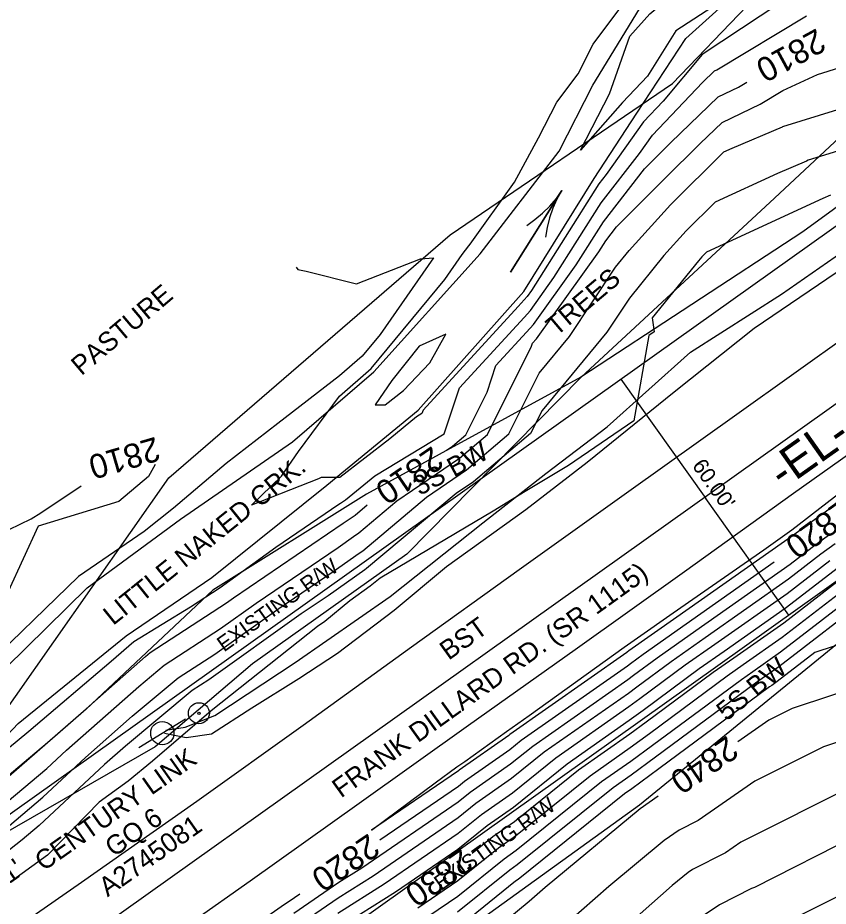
# Model space of a CAD drawing. Extents: x 1284446 to 1285480, y 969739 to 970628.
# Drawn here: x 1284964.9 to 1285132.8, y 970247.2 to 970431.3 of the extents above; entities that cross this region are included whole.
import ezdxf

# ---------------------------------------------------------------- set-up
doc = ezdxf.new("R2010")
doc.units = 0
for name, color, linetype in [('CTL Vertical Benchmark Text', 7, 'Continuous'), ('Default', 7, 'Continuous'), ('Exist Horizontal Alignment', 7, 'Continuous'), ('Exist Horizontal Alignment Direction Label', 7, 'Continuous'), ('Exist Hydro Jurisdictional Stream or Body of Water', 7, 'Continuous'), ('Exist Hydro Jurisdictional Stream or Body of Water Text', 7, 'Continuous'), ('Exist Hydro River Flow Arrow CELL', 7, 'Continuous'), ('Exist Other Culture Anchor (Guy Wire) CELL', 7, 'Continuous'), ('Exist Other Culture Fence Line', 7, 'Continuous'), ('Exist Other Culture Fence Line Text', 7, 'Continuous'), ('Exist Right of Way Line', 7, 'Continuous'), ('Exist Right of Way Line Text', 7, 'Continuous'), ('Exist Right of Way Width CELL', 7, 'Continuous'), ('Exist Roads EOP', 7, 'Continuous'), ('Exist Roads EOP Text', 7, 'Continuous'), ('Exist Structure Minor Pipes CMP 18 Inch Invert', 7, 'Continuous'), ('Exist Utilities Telephone Pole CELL', 7, 'Continuous'), ('Exist Utilities Telephone Pole Text', 7, 'Continuous'), ('Exist Utilities Telephone UG Cable SUE LOS D', 7, 'Continuous'), ('Exist Vegetation Woods Line', 7, 'Continuous'), ('Exist Vegetation Woods Line Text', 7, 'Continuous')]:
    doc.layers.add(name, color=color, linetype=linetype)

msp = doc.modelspace()

# ---------------------------------------------------------------- linework, layer by layer
at = {"layer": 'Default'}
for points in [[(1285120.28, 970455.63), (1285121.11, 970455.54), (1285126.96, 970448.09), (1285127.3, 970447.7), (1285127.28, 970447.63), (1285126.23, 970446.78), (1285126.23, 970446.78), (1285125.3, 970446.03), (1285110.05, 970434.35), (1285101.19, 970428.64), (1285095.32, 970419.2), (1285090.15, 970413.76), (1285081.49, 970403.88), (1285087.46, 970415.58), (1285091.71, 970427.49), (1285095.81, 970432.14), (1285109.31, 970443.37), (1285116.8, 970452.66), (1285120.06, 970455.36), (1285120.28, 970455.63)], [(1285126.82, 970437.08), (1285106.66, 970423.73), (1285098.63, 970414.04), (1285094.53, 970409.73), (1285086.79, 970398.83), (1285085.28, 970396.89), (1285071.3, 970374.78), (1285070.44, 970373.57), (1285068.52, 970371.48), (1285048.83, 970350.01), (1285048.59, 970349.29), (1285047.5, 970348.63), (1285041.93, 970344.09), (1285031.6, 970336.03), (1285027.75, 970336.02), (1285027.2, 970335.78), (1285013.28, 970330.31), (1285019.48, 970336.31), (1285023.01, 970341.45), (1285031.55, 970352.92), (1285038.11, 970358.65), (1285053.33, 970377.1), (1285056.93, 970382.28), (1285058.33, 970384.03), (1285058.58, 970384.39), (1285067.76, 970397.23), (1285072.77, 970406.41), (1285076.59, 970413.81), (1285080.99, 970419.68), (1285084.08, 970425.82), (1285091.1, 970435.21)], [(1284962.76, 970279.8), (1284967.14, 970283.46), (1284984.24, 970298), (1284988.92, 970302.09), (1285000.67, 970309.23), (1285006.8, 970313.22), (1285018.32, 970321.64), (1285031.41, 970330.5), (1285031.76, 970330.75), (1285032.77, 970331.44), (1285038.85, 970336.38), (1285053.24, 970345.07), (1285056.39, 970354.63), (1285069.78, 970369.23), (1285071.08, 970370.65), (1285075.95, 970377.46), (1285085.76, 970392.96), (1285093.66, 970403.17), (1285096.39, 970407.01), (1285106.77, 970417.92), (1285109.23, 970420.29), (1285109.74, 970420.54), (1285128.3, 970431.72)], [(1284954.82, 970262.24), (1284970.86, 970275.72), (1284974.94, 970279.53), (1284989.93, 970292.74), (1284995.2, 970297.13), (1285006.89, 970304.74), (1285014.25, 970309.98), (1285031.23, 970321.54), (1285034.45, 970323.83), (1285035.54, 970324.57), (1285043.44, 970331.18), (1285056.36, 970340.07), (1285062.17, 970344.97), (1285071.31, 970363.26), (1285071.51, 970363.86), (1285072.29, 970364.71), (1285072.37, 970364.79), (1285085.25, 970382.83), (1285086.7, 970385.12), (1285088.9, 970387.96), (1285098.82, 970397.86), (1285106.29, 970405.25), (1285110.8, 970409.62), (1285118.68, 970413.41), (1285123.41, 970416.25), (1285130.57, 970419.59), (1285139.8, 970422.45)], [(1285053.72, 970341.7), (1285054.91, 970342.51), (1285057.71, 970344.88), (1285062.13, 970353.71), (1285063.95, 970359.25), (1285071.03, 970366.97), (1285071.72, 970367.72), (1285080.6, 970380.14), (1285086.23, 970389.04), (1285094.75, 970400.04), (1285097.85, 970403.14), (1285100.18, 970405.45), (1285110.01, 970414.96), (1285114.21, 970416.97), (1285115.91, 970418)], [(1284960.29, 970261.6), (1284970.06, 970269.81), (1284978.88, 970278.04), (1284988.54, 970286.55), (1284998.1, 970294.5), (1285005.67, 970299.43), (1285018.93, 970308.87), (1285030.19, 970316.54), (1285035.6, 970320.39), (1285036.33, 970320.88), (1285049.57, 970331.95), (1285057.82, 970337.62), (1285066.63, 970345.06), (1285072.93, 970357.66), (1285079.2, 970365.24), (1285088.73, 970379.6), (1285091.54, 970383.07), (1285100.14, 970392.56), (1285111.19, 970403.51), (1285112.89, 970404.3), (1285123.32, 970408.72), (1285123.4, 970408.76), (1285138.6, 970413.48)], [(1285137.39, 970404.5), (1285128.62, 970401.78), (1285128.29, 970401.63), (1285122.29, 970399.08), (1285109.38, 970393.12), (1285103.38, 970387.17), (1285098.72, 970382.02), (1285091.59, 970373.23), (1285086.91, 970366.17), (1285073.49, 970349.95), (1285071.09, 970345.15), (1285059.27, 970335.18), (1285055.69, 970332.71), (1285037.12, 970317.19), (1285036.76, 970316.94), (1285029.15, 970311.53), (1285023.6, 970307.76), (1285004.44, 970294.12), (1285000.99, 970291.88), (1284987.16, 970280.37), (1284982.82, 970276.54), (1284969.26, 970263.9), (1284965.76, 970260.95), (1284952.61, 970250.61)], [(1285133.27, 970394.54), (1285131.68, 970393.86), (1285107.57, 970382.72), (1285106.62, 970381.79), (1285105.89, 970380.97), (1285096.29, 970369.12), (1285096.76, 970366.21), (1285095.64, 970365.45), (1285092.53, 970347.78), (1285078.95, 970338.5), (1285070.01, 970333.16), (1285063.34, 970329.04), (1285039.96, 970315.21), (1285037.91, 970313.5), (1285037.91, 970313.5), (1285033.64, 970310.47), (1285028.5, 970306.18), (1285026.96, 970305.16), (1285004.93, 970287.66), (1284992.77, 970277.29), (1284987.74, 970273.12), (1284981.73, 970268.75), (1284971.03, 970257.75), (1284960.47, 970250.16)], [(1285022.54, 970379.63), (1285022.91, 970379.13), (1285024.61, 970378.83), (1285035.05, 970376.18), (1285048.28, 970381.39), (1285050.99, 970381.56), (1285039.97, 970365.7), (1285036.25, 970361.19), (1285031.54, 970357.08), (1285018.78, 970347.26), (1285008.02, 970338.95), (1284997.14, 970329.66), (1284991.08, 970324.83), (1284977.42, 970315.51), (1284970.56, 970308.81), (1284956.23, 970295.03)], [(1285053.53, 970365.76), (1285048.06, 970363.27), (1285042.38, 970356.15), (1285038.91, 970351.08), (1285040.99, 970351.09), (1285044.78, 970354.05), (1285050.22, 970359.82), (1285053.53, 970365.76)], [(1285154.41, 970345.08), (1285130.66, 970327.78), (1285130.22, 970327.47), (1285125.91, 970324.32), (1285125.63, 970324.11), (1285101.41, 970307.07), (1285091.51, 970300.1), (1285091.17, 970299.85), (1285091.08, 970299.79), (1285066.82, 970282.77), (1285066.59, 970282.59), (1285056.29, 970275.37), (1285056.18, 970275.28), (1285038.17, 970262.96), (1285051.32, 970272.8), (1285055.84, 970276.05), (1285057.49, 970277.2), (1285066.13, 970283.44), (1285070.83, 970286.7), (1285090.52, 970300.88), (1285093.25, 970302.81), (1285100.65, 970307.98), (1285119.44, 970321.08), (1285125.23, 970325.18), (1285128.29, 970327.54), (1285129.56, 970328.54), (1285143.87, 970339.56)], [(1284993.35, 970338.77), (1284991.97, 970336.22), (1284985.77, 970331.04), (1284969.06, 970325.96), (1284962.85, 970312.44), (1284950.45, 970302.48), (1284943.38, 970292.88), (1284936.84, 970279.39), (1284935.16, 970275.9), (1284934.66, 970273.98), (1284929.48, 970267.89)], [(1284942.61, 970327.96), (1284916.56, 970308.22), (1284917.2, 970308.11), (1284930.49, 970310.97), (1284939.93, 970314.64), (1284963.11, 970325.3), (1284967.65, 970327.5), (1284969.65, 970328.73), (1284978, 970334.3)], [(1284957.73, 970270.03), (1284971.01, 970281.14), (1284973.1, 970282.91), (1284979.04, 970288.11), (1284991.31, 970298.93), (1284992.31, 970299.76), (1285008.11, 970310.05), (1285009.58, 970311.09), (1285032.27, 970326.55), (1285033.3, 970327.28), (1285034.75, 970328.26), (1285037.25, 970330.36)], [(1285246.88, 970318.65), (1285246.24, 970319.31), (1285245.9, 970319.67), (1285243.44, 970317.45), (1285215.07, 970292.68), (1285197.13, 970303.66), (1285189.33, 970307.48), (1285183.39, 970310.89), (1285162.68, 970326.22), (1285159.7, 970326.4), (1285156.63, 970324.81), (1285140.87, 970313.65), (1285140.29, 970313.23), (1285122.88, 970299.82), (1285117.15, 970295.78), (1285114.8, 970294.14), (1285096.39, 970280.52), (1285091.88, 970277.19), (1285085.84, 970272.96), (1285068.16, 970258.72), (1285065.65, 970256.96), (1285056.02, 970249.2), (1285050.07, 970245.13)], [(1285132.88, 970324.02), (1285129.5, 970321.55), (1285124.94, 970318.04), (1285105.34, 970304.24), (1285097.33, 970298.61), (1285092.47, 970295.02), (1285091.28, 970294.14), (1285071.57, 970280.32), (1285066.98, 970276.62), (1285058.63, 970270.77), (1285056.14, 970268.76), (1285036.16, 970255.1), (1285031.39, 970252.08), (1285022.08, 970245.71)], [(1285134.21, 970322.29), (1285131.3, 970320.16), (1285124.6, 970315), (1285107.31, 970302.83), (1285100.24, 970297.87), (1285093.12, 970292.6), (1285091.38, 970291.31), (1285073.95, 970279.09), (1285067.18, 970273.64), (1285059.8, 970268.46), (1285056.12, 970265.5), (1285038.48, 970253.44), (1285031.28, 970248.89), (1285023.07, 970243.27)], [(1285133.1, 970318.78), (1285124.26, 970311.97), (1285109.28, 970301.42), (1285103.16, 970297.12), (1285093.78, 970290.19), (1285091.48, 970288.49), (1285076.33, 970277.86), (1285067.38, 970270.66), (1285060.97, 970266.16), (1285056.1, 970262.24), (1285040.8, 970251.78), (1285031.17, 970245.7)], [(1285121.61, 970318.48), (1285103.37, 970305.65), (1285094.42, 970299.36), (1285091.82, 970297.43), (1285091.18, 970296.96), (1285069.2, 970281.55), (1285066.79, 970279.6), (1285057.46, 970273.07), (1285056.16, 970272.02), (1285039.88, 970260.88)], [(1285213.52, 970286.83), (1285213.26, 970286.96), (1285194.75, 970298.28), (1285183.09, 970303.99), (1285178.58, 970306.58), (1285162.89, 970318.2), (1285154.21, 970318.74), (1285145.3, 970314.12), (1285142.2, 970311.93), (1285142.09, 970311.84), (1285122.54, 970296.78), (1285119.11, 970294.37), (1285117.71, 970293.39), (1285097.04, 970278.11), (1285091.98, 970274.37), (1285088.22, 970271.73), (1285068.36, 970255.74), (1285066.82, 970254.66), (1285056, 970245.94)], [(1285139.23, 970317.83), (1285138.21, 970317.11), (1285136.69, 970316), (1285123.57, 970305.89), (1285113.21, 970298.6), (1285108.98, 970295.63), (1285095.08, 970285.36), (1285091.68, 970282.84), (1285081.08, 970275.41), (1285067.77, 970264.69), (1285063.31, 970261.56), (1285059.05, 970258.13)], [(1285134.9, 970317.39), (1285123.91, 970308.93), (1285111.24, 970300.01), (1285106.07, 970296.37), (1285094.43, 970287.77), (1285091.58, 970285.67), (1285078.71, 970276.64), (1285067.57, 970267.67), (1285062.14, 970263.86), (1285056.08, 970258.98), (1285043.12, 970250.12), (1285031.06, 970242.51)], [(1285138.49, 970314.62), (1285123.23, 970302.86), (1285115.18, 970297.19), (1285111.89, 970294.88), (1285095.74, 970282.94), (1285091.78, 970280.02), (1285083.46, 970274.18), (1285067.97, 970261.71), (1285064.48, 970259.26), (1285056.04, 970252.46), (1285047.75, 970246.79)], [(1285207.99, 970283.41), (1285207.36, 970283.74), (1285192.38, 970292.91), (1285176.84, 970300.51), (1285173.77, 970302.28), (1285163.09, 970310.18), (1285150.65, 970310.95), (1285148.02, 970306.69), (1285142.04, 970303.74), (1285130.02, 970299.77), (1285122.2, 970293.75), (1285121.08, 970292.96), (1285120.63, 970292.64), (1285097.69, 970275.69), (1285092.08, 970271.54), (1285090.59, 970270.5), (1285068.56, 970252.76), (1285067.99, 970252.36), (1285055.98, 970242.68)], [(1285202.47, 970279.99), (1285201.46, 970280.52), (1285190, 970287.53), (1285170.6, 970297.03), (1285168.97, 970297.97), (1285163.3, 970302.16), (1285156.69, 970302.57), (1285155.29, 970300.31), (1285141.39, 970293.47), (1285125.36, 970288.17), (1285120.52, 970285.75), (1285114.1, 970281.28)], [(1285196.95, 970276.58), (1285195.55, 970277.3), (1285187.63, 970282.15), (1285164.35, 970293.55), (1285164.16, 970293.66), (1285163.5, 970294.15), (1285162.73, 970294.19), (1285162.57, 970293.93), (1285140.75, 970283.19), (1285131.79, 970280.24), (1285117.6, 970273.11), (1285105.88, 970264.97), (1285101.9, 970262.95), (1285098.82, 970260.79), (1285087.32, 970251.28), (1285076, 970241.31)], [(1285191.42, 970273.16), (1285189.65, 970274.08), (1285185.25, 970276.77), (1285171.22, 970283.64), (1285145.48, 970275.56), (1285140.11, 970272.92), (1285138.22, 970272.3), (1285114.68, 970260.48), (1285111.52, 970258.28), (1285104.66, 970254.8), (1285103.77, 970254.18), (1285100.48, 970251.46), (1285081.17, 970234.46)], [(1285185.9, 970269.75), (1285183.75, 970270.86), (1285182.88, 970271.4), (1285180.09, 970272.76), (1285171.59, 970270.09), (1285145.15, 970264.19), (1285138.76, 970261.82), (1285117.53, 970251.11), (1285116.87, 970250.85), (1285110.27, 970247.51), (1285106.27, 970244.77)], [(1285097.59, 970270.01), (1285093.86, 970267.41), (1285074.16, 970251.09), (1285070.83, 970248.16), (1285060.3, 970239.44), (1285058.27, 970237.65), (1285054.34, 970234.91), (1285033.31, 970221.07), (1285031.51, 970219.82), (1285023.14, 970214.32), (1285018.69, 970211.06), (1285017.59, 970210.26)], [(1285170.93, 970258.68), (1285171.39, 970260.03), (1285169.19, 970259.8), (1285152.25, 970256.01), (1285137.15, 970250.41), (1285123.76, 970243.66)], [(1285023.32, 970249.68), (1285021.08, 970248.15), (1285020.16, 970247.57), (1284997.79, 970231.94), (1284995.44, 970230.36), (1284984.5, 970222.71), (1284984.46, 970222.69), (1284962.42, 970207.19), (1284960.1, 970205.06), (1284959.97, 970204.94), (1284953.61, 970200.46), (1284952.11, 970199.61), (1284944, 970192.09), (1284942.47, 970191.14), (1284942.43, 970191.11)]]:
    msp.add_lwpolyline(points, dxfattribs=at)
at = {"layer": 'Exist Horizontal Alignment'}
msp.add_line((1285189.56, 970390.57), (1284976.81, 970239.08), dxfattribs=at)
at = {"layer": 'Exist Hydro Jurisdictional Stream or Body of Water'}
for points in [[(1284873.19, 970156.9), (1284883.51, 970166.48), (1284889.94, 970172.96), (1284895.44, 970190.43), (1284903.3, 970205.95), (1284913.73, 970232), (1284923.66, 970254.25), (1284941.01, 970272.57), (1284958.16, 970292.53), (1284979.26, 970313.17), (1284998.61, 970327.4), (1285021.77, 970343.41), (1285038.64, 970357.96), (1285060.69, 970382.43), (1285077.07, 970403.68), (1285083.99, 970417.36), (1285093.67, 970433.2), (1285120.38, 970455.77)], [(1284898.55, 970093.67), (1284891.93, 970104.57), (1284887.09, 970113.68), (1284882.06, 970129.58), (1284887.8, 970135.61), (1284894.46, 970156.08), (1284893.69, 970164.51), (1284897.37, 970171.05), (1284903.86, 970179.35), (1284904.34, 970180.6), (1284915.98, 970216.96), (1284921.11, 970228.41), (1284932.56, 970248.17), (1284947.31, 970266.45), (1284964.91, 970285.06), (1284987.35, 970303.2), (1285005.06, 970315.3), (1285028.92, 970334.49), (1285047.82, 970349.99), (1285069.69, 970374.61), (1285084.31, 970397.98), (1285093.11, 970411.54), (1285103.27, 970427.02), (1285126.73, 970448.14)]]:
    msp.add_lwpolyline(points, dxfattribs=at)
at = {"layer": 'Exist Hydro River Flow Arrow CELL'}
msp.add_line((1285072.28, 970387.08), (1285072.28, 970387.08), dxfattribs=at)
msp.add_lwpolyline([(1285070.35, 970388.3), (1285072.02, 970389.48), (1285073.62, 970390.81), (1285075.11, 970392.27), (1285076.47, 970393.84), (1285077.63, 970395.53), (1285066.93, 970378.63), (1285077.63, 970395.53), (1285076.59, 970393.76), (1285075.76, 970391.86), (1285075.07, 970389.88), (1285074.56, 970387.87), (1285074.21, 970385.86)], dxfattribs=at)
at = {"layer": 'Exist Other Culture Anchor (Guy Wire) CELL'}
for radius in [2.18, 0.24]:
    msp.add_circle((1285002.4, 970287.2), radius, dxfattribs=at)
at = {"layer": 'Exist Other Culture Fence Line'}
for points in [[(1285182.44, 970426.98), (1285127.53, 970386.93), (1285081.55, 970356.81), (1285037.11, 970332.56), (1285005.28, 970312.73), (1284979.02, 970288.01), (1284954.93, 970267.09)], [(1285144.23, 970309.38), (1285093.66, 970268.13), (1285055.96, 970240.9), (1285022.08, 970217.01), (1284994.2, 970199.4), (1284971, 970182.03), (1284973.25, 970175.79), (1284968.86, 970139.55), (1284964.87, 970125.31)]]:
    msp.add_lwpolyline(points, dxfattribs=at)
at = {"layer": 'Exist Right of Way Line'}
for p, q in [((1285172.16, 970415.01), (1284959.41, 970263.52)), ((1285206.96, 970366.13), (1284994.21, 970214.64))]:
    msp.add_line(p, q, dxfattribs=at)
at = {"layer": 'Exist Right of Way Width CELL'}
for p in [(1285089.84, 970356.39), (1285124.65, 970307.52)]:
    msp.add_line(p, (1285107.43, 970331.7), dxfattribs=at)
at = {"layer": 'Exist Roads EOP'}
for points in [[(1284915.49, 970211.59), (1284915.7, 970211.69), (1284934.18, 970222.25), (1284952.29, 970234.31), (1284978.04, 970252.15), (1285001.96, 970268.99), (1285024.01, 970284.75), (1285046.43, 970300.94), (1285068.79, 970317), (1285091.5, 970333.21), (1285113.88, 970349.18), (1285137.46, 970366.05), (1285160.86, 970382.78), (1285183.61, 970398.87)], [(1284906.42, 970183.31), (1284909.89, 970185.39), (1284925.09, 970194), (1284944.45, 970205.72), (1284965.49, 970219.25), (1284989.1, 970235.63), (1285013.02, 970252.46), (1285035.6, 970268.52), (1285058.25, 970284.75), (1285080.34, 970300.38), (1285103.05, 970316.58), (1285125.6, 970332.83), (1285149.35, 970349.65), (1285172.35, 970366.09), (1285195.52, 970382.27)]]:
    msp.add_lwpolyline(points, dxfattribs=at)
at = {"layer": 'Exist Utilities Telephone Pole CELL'}
for p, q in [((1284989.97, 970280.12), (1284999.65, 970286.01)), ((1284994.81, 970283.06), (1284994.81, 970283.06))]:
    msp.add_line(p, q, dxfattribs=at)
msp.add_circle((1284994.81, 970283.06), 2.41, dxfattribs=at)
at = {"layer": 'Exist Utilities Telephone UG Cable SUE LOS D'}
for points in [[(1284995.56, 970283.65), (1284999.52, 970284.32), (1285005.72, 970286.69), (1285022.35, 970297.73), (1285042.02, 970311.35), (1285061.21, 970326.65), (1285074.25, 970336.9), (1285086.97, 970346.55), (1285104.29, 970362.01), (1285123.12, 970374.03), (1285145.38, 970389.54), (1285157.44, 970398.83)], [(1284995.24, 970283.08), (1284999.73, 970282.13), (1285005, 970282.93), (1285013.35, 970288.3), (1285023.1, 970294.39), (1285031.08, 970299.64), (1285042.84, 970308.55), (1285053.73, 970317.61), (1285070.11, 970329.42), (1285082.83, 970339.22), (1285100.9, 970353.83), (1285117.45, 970367.01), (1285136.41, 970379.81), (1285147.73, 970387.67), (1285161, 970397.03)]]:
    msp.add_lwpolyline(points, dxfattribs=at)
at = {"layer": 'Exist Vegetation Woods Line'}
msp.add_lwpolyline([(1285171.52, 970440.57), (1285121.64, 970393.92), (1285081.63, 970356.87), (1285045.47, 970320.17), (1285013.5, 970297.41), (1284993.36, 970280.22), (1284932.55, 970245.36), (1284996.18, 970336), (1285054.45, 970386.33), (1285100.52, 970417.69), (1285131.32, 970449.81)], dxfattribs=at)

# ---------------------------------------------------------------- texts
at = {"layer": 'CTL Vertical Benchmark Text'}
msp.add_text("ELEVATION = 2812.79'", height=4, rotation=27.3235, dxfattribs=at).set_placement((1284926.08, 970426.58))
at = {"layer": 'Default'}
for s, rotation, p in [('2810', 208.4942, (1285130.43, 970429.23)), ('2810', 196.2232, (1284993.43, 970344.53)), ('2810', 214.545, (1285050.76, 970342.7)), ('2820', 215.9393, (1285135.47, 970331.66)), ('2840', 214.3283, (1285111.88, 970282.69)), ('2820', 214.091, (1285037.58, 970262.41)), ('2830', 214.8842, (1285056.83, 970259.37))]:
    msp.add_text(s, height=5, rotation=rotation, dxfattribs=at).set_placement(p)
at = {"layer": 'Exist Horizontal Alignment Direction Label'}
msp.add_text('-EL-', height=7, rotation=35.2154, dxfattribs=at).set_placement((1285123.45, 970333.49))
at = {"layer": 'Exist Hydro Jurisdictional Stream or Body of Water Text'}
msp.add_text('LITTLE NAKED CRK.', height=4, rotation=38.8027, dxfattribs=at).set_placement((1284984.62, 970305.26))
at = {"layer": 'Exist Other Culture Fence Line Text'}
for s, rotation, p in [('3S BW', 28.6218, (1285048.17, 970332.2)), ('5S BW', 39.2033, (1285111.7, 970285.42))]:
    msp.add_text(s, height=4, rotation=rotation, dxfattribs=at).set_placement(p)
at = {"layer": 'Exist Right of Way Line Text'}
for p in [(1285007.59, 970299.78), (1285052.58, 970250.31)]:
    msp.add_text('EXISTING R/W', height=3.2, rotation=35.4528, dxfattribs=at).set_placement(p)
at = {"layer": 'Exist Right of Way Width CELL'}
msp.add_text("60.00'", height=3.2, rotation=305.4528, dxfattribs=at).set_placement((1285104.47, 970338.47))
at = {"layer": 'Exist Roads EOP Text'}
for s, rotation, p in [('FRANK DILLARD RD. (SR 1115)', 35.6914, (1285031.85, 970269.51)), ('BST', 35.6035, (1285054.14, 970298.05))]:
    msp.add_text(s, height=4, rotation=rotation, dxfattribs=at).set_placement(p)
at = {"layer": 'Exist Structure Minor Pipes CMP 18 Inch Invert'}
msp.add_text("INV=2814.31'", height=4, rotation=34.8371, dxfattribs=at).set_placement((1284939.77, 970235.52))
at = {"layer": 'Exist Utilities Telephone Pole Text'}
for s, p in [('CENTURY LINK', (1284970.2, 970254.35)), ('GQ 6', (1284984.76, 970257.26)), ('A2745081', (1284983.47, 970249.02))]:
    msp.add_text(s, height=4, rotation=35.1662, dxfattribs=at).set_placement(p)
at = {"layer": 'Exist Vegetation Woods Line Text'}
for s, p in [('TREES', (1285076.46, 970365.21)), ('PASTURE', (1284978.05, 970357.02))]:
    msp.add_text(s, height=4, rotation=40.2069, dxfattribs=at).set_placement(p)

doc.saveas('drawing.dxf')
